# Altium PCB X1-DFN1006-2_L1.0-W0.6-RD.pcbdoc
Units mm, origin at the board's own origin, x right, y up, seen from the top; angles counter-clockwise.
Board outline 14.41 x 13.72 mm, 2 copper layers (Top Layer, Bottom Layer), stack 0 mm thick; 1 components, 0 nets, 2 pads, 0 vias.
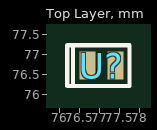
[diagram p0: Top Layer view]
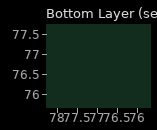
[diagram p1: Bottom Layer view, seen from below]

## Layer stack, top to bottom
Top Layer: signal copper (thickness not stored)
Bottom Layer: signal copper (thickness not stored)

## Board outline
84.255,69.85 69.85,69.85 69.85,83.57 84.255,83.57

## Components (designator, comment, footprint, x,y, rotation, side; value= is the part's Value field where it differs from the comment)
U? "" X1-DFN1006-2_L1.0-W0.6-RD 77.05,76.71 r0 top

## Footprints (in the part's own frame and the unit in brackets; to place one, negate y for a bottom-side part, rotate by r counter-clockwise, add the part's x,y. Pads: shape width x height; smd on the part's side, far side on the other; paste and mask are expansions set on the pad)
X1-DFN1006-2_L1.0-W0.6-RD [mm]
  rect 0.4x0.7 smd: 1(-0.35,0) 2(0.35,0)
  silkscreen extent -0.85,-0.51 0.71,0.51

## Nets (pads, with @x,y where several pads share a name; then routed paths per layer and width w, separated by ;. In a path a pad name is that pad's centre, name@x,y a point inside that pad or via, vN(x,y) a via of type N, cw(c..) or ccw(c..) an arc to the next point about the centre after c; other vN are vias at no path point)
pads on no net: U?.1 U?.2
